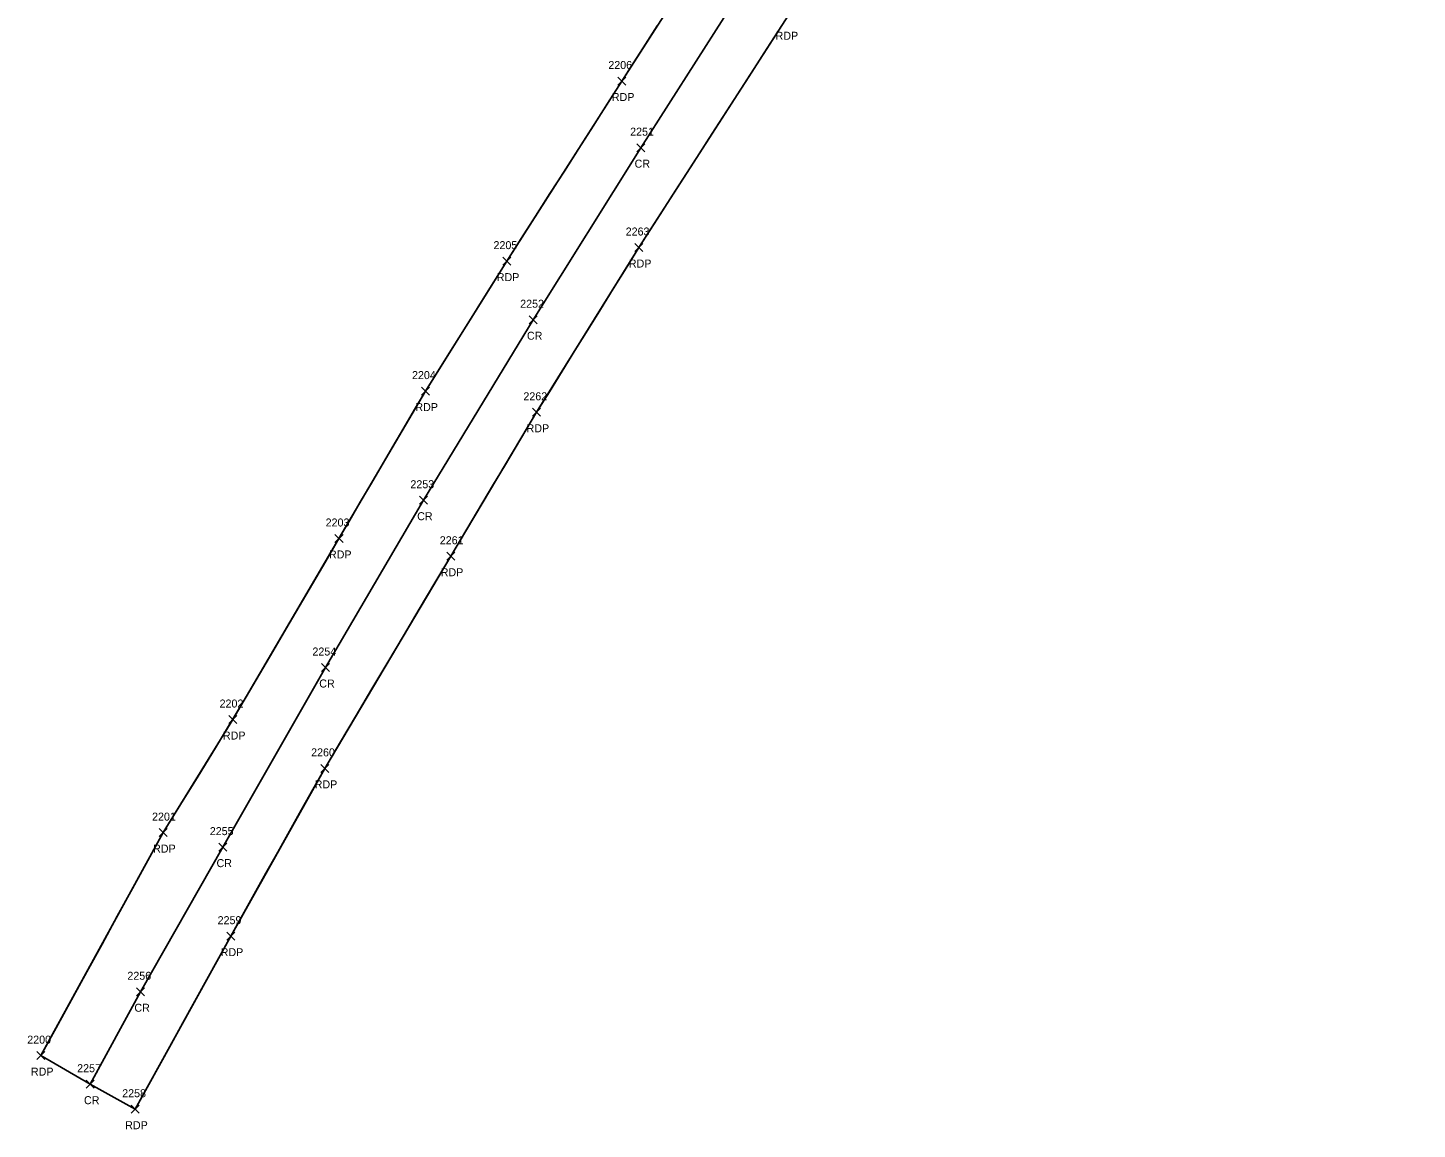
# Model space of a CAD drawing. Extents: x 1638344 to 1639591, y 610835 to 612202.
# Drawn here: x 1638851.5 to 1639198.8, y 610834.8 to 611110.3 of the extents above; entities that cross this region are included whole.
import ezdxf

# ---------------------------------------------------------------- set-up
doc = ezdxf.new("R2010")
doc.units = 0
for name, color, linetype in [('LSOGP', 7, 'Continuous'), ('P_A', 7, 'Continuous'), ('P_I', 7, 'Continuous'), ('P_TIC', 7, 'Continuous'), ('PET', 7, 'Continuous'), ('PRC', 7, 'Continuous')]:
    doc.layers.add(name, color=color, linetype=linetype)

msp = doc.modelspace()

# ---------------------------------------------------------------- linework, layer by layer
at = {"layer": 'LSOGP'}
msp.add_lwpolyline([(1639008.86, 611110.74), (1639005.92, 611106.15), (1639002.98, 611101.56), (1639000.04, 611096.97), (1638996.45, 611091.34), (1638992.85, 611085.71), (1638989.26, 611080.07), (1638985.66, 611074.44), (1638982.07, 611068.81), (1638978.47, 611063.18), (1638974.88, 611057.55), (1638971.29, 611051.92), (1638966.19, 611043.8), (1638961.1, 611035.67), (1638956.01, 611027.55), (1638950.92, 611019.42), (1638948.22, 611014.82), (1638945.52, 611010.21), (1638942.82, 611005.6), (1638940.12, 611000.99), (1638937.43, 610996.38), (1638934.73, 610991.78), (1638932.03, 610987.17), (1638929.33, 610982.56), (1638926.02, 610976.9), (1638922.7, 610971.24), (1638919.39, 610965.58), (1638916.07, 610959.92), (1638912.76, 610954.26), (1638909.45, 610948.6), (1638906.13, 610942.94), (1638898.46, 610930.21), (1638894.09, 610923.14), (1638889.73, 610916.07), (1638885.37, 610909), (1638881.55, 610902.03), (1638877.74, 610895.06), (1638873.92, 610888.08), (1638870.1, 610881.11), (1638866.28, 610874.14), (1638862.46, 610867.17), (1638858.65, 610860.19), (1638854.83, 610853.22), (1638867.14, 610846.08), (1638878.4, 610839.82), (1638881.38, 610845.23), (1638884.37, 610850.64), (1638887.35, 610856.05), (1638890.33, 610861.46), (1638893.31, 610866.87), (1638896.3, 610872.28), (1638899.28, 610877.69), (1638902.26, 610883.1), (1638905.2, 610888.35), (1638908.13, 610893.59), (1638911.07, 610898.84), (1638914.01, 610904.08), (1638916.95, 610909.33), (1638919.88, 610914.58), (1638922.82, 610919.82), (1638925.76, 610925.07), (1638929.7, 610931.7), (1638933.63, 610938.33), (1638937.57, 610944.96), (1638941.51, 610951.59), (1638945.44, 610958.23), (1638949.38, 610964.86), (1638953.32, 610971.49), (1638957.26, 610978.12), (1638959.94, 610982.62), (1638962.62, 610987.12), (1638965.31, 610991.62), (1638967.99, 610996.12), (1638970.68, 611000.62), (1638973.36, 611005.12), (1638976.04, 611009.62), (1638978.73, 611014.12), (1638981.92, 611019.27), (1638985.12, 611024.42), (1638988.31, 611029.57), (1638991.51, 611034.72), (1638994.71, 611039.87), (1638997.9, 611045.02), (1639001.1, 611050.17), (1639004.29, 611055.33), (1639008.88, 611062.45), (1639013.46, 611069.57), (1639018.05, 611076.69), (1639022.63, 611083.81), (1639027.21, 611090.93), (1639031.8, 611098.05), (1639036.38, 611105.17), (1639040.97, 611112.29)], dxfattribs=at)
at = {"layer": 'P_TIC'}
for points in [[(1638999.04, 611095.97), (1639001.04, 611097.97)], [(1639001.04, 611095.97), (1638999.04, 611097.97)], [(1639003.79, 611079.3), (1639005.79, 611081.3)], [(1639005.79, 611079.3), (1639003.79, 611081.3)], [(1639003.29, 611054.33), (1639005.29, 611056.33)], [(1639005.29, 611054.33), (1639003.29, 611056.33)], [(1638970.29, 611050.92), (1638972.29, 611052.92)], [(1638972.29, 611050.92), (1638970.29, 611052.92)], [(1638976.88, 611036.27), (1638978.88, 611038.27)], [(1638978.88, 611036.27), (1638976.88, 611038.27)], [(1638949.92, 611018.42), (1638951.92, 611020.42)], [(1638951.92, 611018.42), (1638949.92, 611020.42)], [(1638977.73, 611013.12), (1638979.73, 611015.12)], [(1638979.73, 611013.12), (1638977.73, 611015.12)], [(1638949.44, 610991.13), (1638951.44, 610993.13)], [(1638951.44, 610991.13), (1638949.44, 610993.13)], [(1638928.33, 610981.56), (1638930.33, 610983.56)], [(1638930.33, 610981.56), (1638928.33, 610983.56)], [(1638956.26, 610977.12), (1638958.26, 610979.12)], [(1638958.26, 610977.12), (1638956.26, 610979.12)], [(1638924.95, 610949.29), (1638926.95, 610951.29)], [(1638926.95, 610949.29), (1638924.95, 610951.29)], [(1638901.82, 610936.28), (1638903.82, 610938.28)], [(1638903.82, 610936.28), (1638901.82, 610938.28)], [(1638924.76, 610924.07), (1638926.76, 610926.07)], [(1638926.76, 610924.07), (1638924.76, 610926.07)], [(1638884.37, 610908), (1638886.37, 610910)], [(1638886.37, 610908), (1638884.37, 610910)], [(1638899.28, 610904.37), (1638901.28, 610906.37)], [(1638901.28, 610904.37), (1638899.28, 610906.37)], [(1638901.26, 610882.1), (1638903.26, 610884.1)], [(1638903.26, 610882.1), (1638901.26, 610884.1)], [(1638878.75, 610868.2), (1638880.75, 610870.2)], [(1638880.75, 610868.2), (1638878.75, 610870.2)], [(1638853.83, 610852.22), (1638855.83, 610854.22)], [(1638855.83, 610852.22), (1638853.83, 610854.22)], [(1638866.14, 610845.08), (1638868.14, 610847.08)], [(1638868.14, 610845.08), (1638866.14, 610847.08)], [(1638877.4, 610838.82), (1638879.4, 610840.82)], [(1638879.4, 610838.82), (1638877.4, 610840.82)]]:
    msp.add_lwpolyline(points, dxfattribs=at)
at = {"layer": 'PET'}
for points in [[(1638854.83, 610853.22), (1638885.37, 610909), (1638902.82, 610937.28), (1638929.33, 610982.56), (1638950.92, 611019.42), (1638971.29, 611051.92), (1639000.04, 611096.97), (1639023.57, 611133.7), (1639039.12, 611159.19), (1639064.62, 611197.79), (1639080.51, 611223.3), (1639114.23, 611277.34), (1639131.17, 611302.28), (1639149.64, 611331.79), (1639176.42, 611372.36), (1639193.48, 611398.88)], [(1638878.4, 610839.82), (1638902.26, 610883.1), (1638925.76, 610925.07), (1638957.26, 610978.12), (1638978.73, 611014.12), (1639004.29, 611055.33), (1639040.97, 611112.29), (1639073.41, 611162.89), (1639102.56, 611207.56), (1639124.27, 611240.99), (1639140.69, 611264.29), (1639156.2, 611287.4), (1639175.63, 611318.1), (1639189.77, 611341.61), (1639219.88, 611389.38)]]:
    msp.add_lwpolyline(points, dxfattribs=at)
at = {"layer": 'PRC'}
msp.add_lwpolyline([(1639222.36, 611418.19), (1639195.34, 611376.27), (1639169.71, 611336.75), (1639147.17, 611302.78), (1639120.59, 611261.17), (1639092.55, 611217.83), (1639063.71, 611172.41), (1639032.46, 611123.7), (1639004.79, 611080.3), (1638977.88, 611037.27), (1638950.44, 610992.13), (1638925.95, 610950.29), (1638900.28, 610905.37), (1638879.75, 610869.2), (1638867.14, 610846.08)], dxfattribs=at)

# ---------------------------------------------------------------- texts
at = {"layer": 'P_A'}
for s, p in [('RDP', (1639038.46, 611107.29)), ('RDP', (1638997.53, 611091.97)), ('CR', (1639003.22, 611075.3)), ('RDP', (1639001.78, 611050.33)), ('RDP', (1638968.77, 611046.92)), ('CR', (1638976.31, 611032.27)), ('RDP', (1638948.41, 611014.42)), ('RDP', (1638976.22, 611009.12)), ('CR', (1638948.87, 610987.13)), ('RDP', (1638926.82, 610977.56)), ('RDP', (1638954.75, 610973.12)), ('CR', (1638924.39, 610945.29)), ('RDP', (1638900.31, 610932.28)), ('RDP', (1638923.25, 610920.07)), ('RDP', (1638882.86, 610904)), ('CR', (1638898.72, 610900.37)), ('RDP', (1638899.75, 610878.1)), ('CR', (1638878.18, 610864.2)), ('RDP', (1638852.32, 610848.22)), ('CR', (1638865.58, 610841.08)), ('RDP', (1638875.89, 610834.82))]:
    msp.add_text(s, height=2, dxfattribs=at).set_placement(p)
at = {"layer": 'P_I'}
for s, p in [('2206', (1638996.65, 611099.97)), ('2251', (1639002.1, 611083.3)), ('2263', (1639000.99, 611058.33)), ('2205', (1638967.95, 611054.92)), ('2252', (1638974.62, 611040.27)), ('2204', (1638947.58, 611022.42)), ('2262', (1638975.42, 611017.12)), ('2253', (1638947.18, 610995.13)), ('2203', (1638925.99, 610985.56)), ('2261', (1638954.52, 610981.12)), ('2254', (1638922.69, 610953.29)), ('2202', (1638899.48, 610940.28)), ('2260', (1638922.36, 610928.07)), ('2201', (1638882.6, 610912)), ('2255', (1638897.03, 610908.37)), ('2259', (1638898.99, 610886.1)), ('2256', (1638876.43, 610872.2)), ('2200', (1638851.4, 610856.22)), ('2257', (1638863.88, 610849.08)), ('2258', (1638875.14, 610842.82))]:
    msp.add_text(s, height=2, dxfattribs=at).set_placement(p)

doc.saveas('drawing.dxf')
